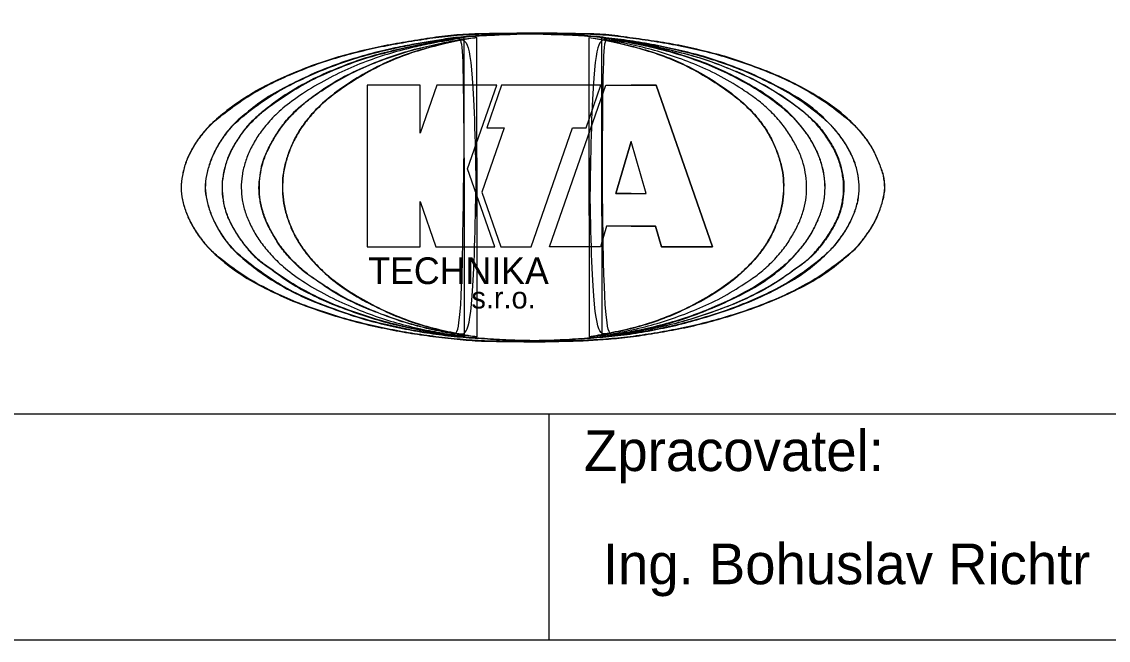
# Model space of a CAD drawing. Extents: x 25 to 46, y -50 to -20.3.
# Drawn here: x 37.705 to 42.505, y -39.8 to -37.068 of the extents above; entities that cross this region are included whole.
import ezdxf

# ---------------------------------------------------------------- set-up
doc = ezdxf.new("R2010")
doc.units = 0
doc.layers.add('_popis', color=7, linetype='Continuous')
doc.layers.add('Rozpiska_pole_6', color=7, linetype='Continuous')

msp = doc.modelspace()

# ---------------------------------------------------------------- linework, layer by layer
at = {"layer": '_popis'}
for p, q in [((39.2313, -37.3488), (39.2313, -38.0628)), ((39.465, -37.3488), (39.2313, -37.3488)), ((39.5386, -37.3488), (39.465, -37.5605)), ((39.465, -37.5605), (39.465, -37.3488)), ((39.8036, -37.3488), (39.5386, -37.3488)), ((39.675, -37.7182), (39.8036, -37.3488)), ((39.825, -37.3488), (39.7594, -37.5375)), ((40.2641, -37.3488), (39.825, -37.3488)), ((40.037, -38.0626), (40.2855, -37.3488)), ((40.1984, -37.5375), (40.2641, -37.3488)), ((40.2855, -37.3488), (40.3969, -37.3488)), ((40.3969, -37.3488), (40.5083, -37.3488)), ((40.5083, -37.3488), (40.7567, -38.0626)), ((39.8369, -37.5375), (39.7381, -37.8213)), ((39.7594, -37.5375), (39.8369, -37.5375)), ((39.9551, -38.0628), (40.1379, -37.5375)), ((40.1379, -37.5375), (40.1984, -37.5375)), ((40.3969, -37.5973), (40.3305, -37.8269)), ((40.4633, -37.8269), (40.3969, -37.5973)), ((39.795, -38.0628), (39.675, -37.7182)), ((39.7381, -37.8213), (39.8222, -38.0628)), ((39.465, -38.0628), (39.465, -37.8616)), ((39.465, -37.8616), (39.535, -38.0628)), ((40.3305, -37.8269), (40.3969, -37.8269)), ((40.3969, -37.8269), (40.4633, -37.8269)), ((40.2887, -37.9716), (40.2623, -38.0628)), ((40.3969, -37.9716), (40.2887, -37.9716)), ((40.5051, -37.9716), (40.3969, -37.9716)), ((40.5315, -38.0628), (40.5051, -37.9716)), ((39.2313, -38.0628), (39.465, -38.0628)), ((39.535, -38.0628), (39.795, -38.0628)), ((39.8222, -38.0628), (39.9551, -38.0628)), ((40.2623, -38.0628), (40.037, -38.0626)), ((40.7567, -38.0626), (40.5315, -38.0628))]:
    msp.add_line(p, q, dxfattribs=at)
for points in [[(39.2313, -37.3488), (39.2313, -38.0628), (39.465, -38.0628), (39.465, -37.8616), (39.535, -38.0628), (39.795, -38.0628), (39.675, -37.7182), (39.8036, -37.3488), (39.5386, -37.3488), (39.465, -37.5605), (39.465, -37.3488), (39.2313, -37.3488)], [(39.825, -37.3488), (39.7594, -37.5375), (39.8369, -37.5375), (39.7381, -37.8213), (39.8222, -38.0628), (39.9551, -38.0628), (40.1379, -37.5375), (40.1984, -37.5375), (40.2641, -37.3488), (39.825, -37.3488)], [(40.3969, -37.9716), (40.2887, -37.9716), (40.2623, -38.0628), (40.037, -38.0626), (40.2855, -37.3488), (40.3969, -37.3488)], [(40.3969, -37.9716), (40.5051, -37.9716), (40.5315, -38.0628), (40.7567, -38.0626), (40.5083, -37.3488), (40.3969, -37.3488)], [(40.3969, -37.8269), (40.3305, -37.8269), (40.3969, -37.5973)], [(40.3969, -37.8269), (40.4633, -37.8269), (40.3969, -37.5973)]]:
    msp.add_lwpolyline(points, dxfattribs=at)
for points, degree in [([(39.9639, -37.1182), (39.9235, -37.1188), (39.852, -37.1199), (39.7448, -37.1208), (39.642, -37.1242), (39.5347, -37.1357), (39.4277, -37.1537), (39.3201, -37.1713), (39.2128, -37.1946), (39.1051, -37.2223), (38.9975, -37.2573), (38.8906, -37.3005), (38.7817, -37.3493), (38.6736, -37.4136), (38.589, -37.4768), (38.5246, -37.5353), (38.4849, -37.5846), (38.452, -37.639), (38.4265, -37.6924), (38.4148, -37.7474), (38.4067, -37.8011), (38.4133, -37.8559), (38.4303, -37.9096), (38.4542, -37.9643), (38.4893, -38.0177), (38.5268, -38.0666), (38.5904, -38.1238), (38.6724, -38.1873), (38.7823, -38.2472), (38.8896, -38.2978), (38.9979, -38.3377), (39.1054, -38.3729), (39.2125, -38.4023), (39.3197, -38.4256), (39.427, -38.4454), (39.5348, -38.4603), (39.6419, -38.4721), (39.7493, -38.4805), (39.8565, -38.4792), (39.9639, -38.483), (40.0712, -38.4798), (40.1532, -38.4786), (40.1993, -38.4763), (40.2097, -38.4757)], 3), ([(39.9639, -37.1182), (39.8427, -37.1199), (39.7495, -37.1211), (39.6423, -37.1255), (39.5351, -37.1368), (39.4279, -37.1536), (39.3205, -37.1722), (39.2133, -37.1952), (39.1061, -37.2232), (38.9987, -37.2583), (38.8915, -37.3009), (38.7849, -37.3503), (38.6775, -37.4138), (38.5703, -37.4945), (38.5286, -37.5334), (38.4849, -37.5873), (38.4523, -37.6406), (38.4282, -37.6944), (38.4153, -37.7478), (38.4091, -37.8015), (38.4147, -37.8543), (38.431, -37.9085), (38.4551, -37.9623), (38.4888, -38.0156), (38.532, -38.0694), (38.5702, -38.1052), (38.6774, -38.1865), (38.7846, -38.2471), (38.8906, -38.2964), (38.9989, -38.3373), (39.1065, -38.3723), (39.2131, -38.4014), (39.3197, -38.425), (39.4275, -38.4446), (39.535, -38.4598), (39.6427, -38.4716), (39.7487, -38.4789), (39.8568, -38.4801), (39.9639, -38.4818), (40.0711, -38.4801), (40.1786, -38.4773), (40.2858, -38.4705), (40.3924, -38.4605), (40.4999, -38.4442), (40.6071, -38.4251), (40.7143, -38.401), (40.8218, -38.3713), (40.929, -38.336), (41.0362, -38.2945), (41.1428, -38.2446), (41.2508, -38.1813), (41.3585, -38.0978), (41.3905, -38.0692), (41.4326, -38.0159), (41.468, -37.9626), (41.4928, -37.9085), (41.5102, -37.8552), (41.5187, -37.8015), (41.5124, -37.748), (41.4939, -37.6942), (41.4698, -37.6394), (41.4378, -37.5872), (41.3924, -37.5334), (41.3593, -37.5009), (41.2509, -37.417), (41.1437, -37.3537), (41.0373, -37.3029), (40.9295, -37.2614), (40.8218, -37.2244), (40.7152, -37.1964), (40.6071, -37.1722), (40.4994, -37.1537), (40.3917, -37.1386), (40.2853, -37.125), (40.1784, -37.1211), (40.0713, -37.1192), (39.9639, -37.1182), (39.9639, -37.1182), (39.9639, -37.1182)], 3), ([(39.9639, -37.1211), (39.9997, -37.1226), (40.0713, -37.1255), (40.1787, -37.1265), (40.2858, -37.1383), (40.393, -37.1519), (40.5005, -37.1698), (40.6076, -37.1935), (40.7158, -37.2191), (40.8227, -37.2556), (40.9309, -37.2969), (41.0378, -37.3497), (41.1493, -37.4096), (41.2316, -37.4752), (41.2925, -37.5363), (41.331, -37.5848), (41.364, -37.639), (41.3885, -37.6928), (41.4013, -37.7476), (41.406, -37.8017), (41.4019, -37.8563), (41.3856, -37.9101), (41.3615, -37.9642), (41.3273, -38.0178), (41.2909, -38.0655), (41.2291, -38.1234), (41.1493, -38.1893), (41.0386, -38.2517), (40.9304, -38.3018), (40.8228, -38.3436), (40.715, -38.3773), (40.6078, -38.4072), (40.5001, -38.4295), (40.393, -38.4491), (40.2855, -38.4596), (40.1784, -38.4688), (40.0713, -38.4757), (39.9639, -38.4792), (39.8566, -38.4751), (39.7494, -38.4675), (39.6419, -38.4616), (39.5346, -38.4489), (39.4272, -38.4315), (39.3199, -38.4087), (39.2119, -38.3821), (39.1053, -38.3453), (38.9969, -38.3064), (38.8884, -38.2571), (38.7805, -38.1918), (38.696, -38.1276), (38.6313, -38.0686), (38.5928, -38.0182), (38.5608, -37.9637), (38.5367, -37.9099), (38.5218, -37.8558), (38.5123, -37.8015), (38.5206, -37.7471), (38.5345, -37.693), (38.5572, -37.6389), (38.589, -37.5849), (38.6276, -37.5322), (38.6946, -37.4726), (38.7792, -37.4054), (38.8901, -37.3461), (38.997, -37.2943), (39.1048, -37.2523), (39.2124, -37.218), (39.32, -37.1904), (39.4116, -37.1723), (39.4832, -37.1591), (39.5546, -37.1477), (39.6419, -37.1348), (39.7494, -37.1281), (39.8567, -37.1236), (39.9282, -37.122), (39.9639, -37.1211)], 3), ([(39.9639, -37.1211), (39.8567, -37.124), (39.7495, -37.1284), (39.6423, -37.1363), (39.5351, -37.1509), (39.4869, -37.1587), (39.428, -37.1694), (39.3205, -37.1913), (39.2133, -37.2188), (39.1059, -37.2532), (38.9988, -37.2952), (38.8914, -37.3463), (38.7848, -37.4063), (38.6775, -37.4883), (38.6298, -37.5333), (38.5888, -37.5872), (38.558, -37.6404), (38.5355, -37.6944), (38.5215, -37.7477), (38.5153, -37.8015), (38.5226, -37.8551), (38.5377, -37.9083), (38.5613, -37.9622), (38.5928, -38.0158), (38.6349, -38.0696), (38.6775, -38.11), (38.7847, -38.1919), (38.8914, -38.256), (38.9986, -38.3054), (39.1058, -38.3452), (39.2132, -38.3807), (39.3204, -38.4082), (39.4276, -38.4306), (39.535, -38.4482), (39.6422, -38.4605), (39.7494, -38.4678), (39.8567, -38.4745), (39.9639, -38.4779), (40.0711, -38.4751), (40.1786, -38.4684), (40.2852, -38.4594), (40.3924, -38.4476), (40.4999, -38.4291), (40.607, -38.4061), (40.7142, -38.3769), (40.8217, -38.3426), (40.9289, -38.3011), (41.0361, -38.2512), (41.1435, -38.1886), (41.2507, -38.1028), (41.285, -38.0695), (41.3277, -38.0156), (41.3608, -37.9624), (41.3849, -37.9085), (41.4, -37.8553), (41.4045, -37.802), (41.4, -37.7479), (41.3871, -37.6947), (41.3636, -37.6408), (41.331, -37.5872), (41.2883, -37.5333), (41.2507, -37.4952), (41.1436, -37.4105), (41.0362, -37.3496), (40.929, -37.298), (40.8218, -37.256), (40.7144, -37.2206), (40.6073, -37.1937), (40.5001, -37.1707), (40.3926, -37.1526), (40.2855, -37.1385), (40.1786, -37.1283), (40.0714, -37.1249), (39.9639, -37.1211), (39.9639, -37.1211), (39.9639, -37.1211)], 3), ([(39.6598, -37.1392), (39.6542, -37.1395), (39.6124, -37.142), (39.5349, -37.1558), (39.4279, -37.1771), (39.3197, -37.2014), (39.2116, -37.2305), (39.1047, -37.2712), (38.9961, -37.3167), (38.8874, -37.3779), (38.8068, -37.4345), (38.7427, -37.4867), (38.6988, -37.5289), (38.6605, -37.5856), (38.6272, -37.6379), (38.6063, -37.6931), (38.5939, -37.7473), (38.5881, -37.8016), (38.5941, -37.8555), (38.605, -37.9105), (38.6297, -37.9637), (38.6615, -38.0175), (38.7024, -38.072), (38.7425, -38.1172), (38.8103, -38.1619), (38.8864, -38.2219), (38.9959, -38.2806), (39.1038, -38.3273), (39.2116, -38.3644), (39.3184, -38.3987), (39.4269, -38.4217), (39.5198, -38.4409), (39.5976, -38.4528), (39.6396, -38.4563), (39.6602, -38.458)], 3), ([(39.6602, -38.458), (39.5987, -38.4522), (39.5345, -38.4427), (39.4273, -38.4217), (39.3195, -38.397), (39.212, -38.3641), (39.1053, -38.3263), (38.9986, -38.2801), (38.891, -38.2205), (38.7832, -38.1443), (38.7543, -38.1238), (38.7017, -38.0697), (38.6611, -38.0148), (38.6301, -37.9622), (38.6069, -37.9092), (38.5948, -37.8548), (38.59, -37.8012), (38.5948, -37.7486), (38.6074, -37.694), (38.6284, -37.64), (38.66, -37.587), (38.6984, -37.5334), (38.753, -37.4787), (38.7825, -37.4546), (38.891, -37.3782), (38.9993, -37.3178), (39.1062, -37.2713), (39.2118, -37.2324), (39.3215, -37.2018), (39.4277, -37.1776), (39.5355, -37.1561), (39.643, -37.1403), (39.6598, -37.1392), (39.6602, -38.458), (39.6598, -37.1392)], 3), ([(39.6598, -37.1392), (39.5441, -37.1576), (39.4279, -37.1817), (39.3201, -37.2112), (39.2125, -37.2476), (39.1063, -37.2938), (38.9991, -37.3506), (38.8916, -37.4218), (38.8243, -37.4796), (38.7764, -37.5337), (38.7386, -37.5868), (38.7102, -37.6399), (38.6896, -37.6943), (38.6775, -37.7484), (38.6738, -37.8014), (38.678, -37.8554), (38.6912, -37.9085), (38.7133, -37.9621), (38.7422, -38.0162), (38.7811, -38.0693), (38.829, -38.1228), (38.8926, -38.1785), (38.9988, -38.2489), (39.1066, -38.3041), (39.2136, -38.3496), (39.3208, -38.3874), (39.4276, -38.4163), (39.5351, -38.4385), (39.6113, -38.4511), (39.6602, -38.458), (39.6598, -37.1392), (39.6602, -38.458)], 3), ([(39.7161, -38.4596), (39.6914, -38.4575), (39.6304, -38.4523), (39.5347, -38.4318), (39.4265, -38.4074), (39.3198, -38.3704), (39.2116, -38.3288), (39.1018, -38.2769), (39.021, -38.2196), (38.9493, -38.1723), (38.9019, -38.1253), (38.8532, -38.0728), (38.8201, -38.0165), (38.7893, -37.964), (38.7686, -37.9101), (38.7572, -37.8559), (38.7513, -37.8017), (38.7578, -37.7476), (38.7662, -37.6929), (38.7884, -37.6393), (38.817, -37.5858), (38.8518, -37.5308), (38.8972, -37.476), (38.9485, -37.4304), (39.0183, -37.3777), (39.1027, -37.3224), (39.2113, -37.2692), (39.3191, -37.2272), (39.4263, -37.1919), (39.5343, -37.1674), (39.6305, -37.1475), (39.6915, -37.1406), (39.7161, -37.1377)], 3), ([(39.7161, -38.4596), (39.6424, -38.452), (39.5346, -38.4316), (39.4284, -38.4058), (39.3206, -38.3701), (39.2131, -38.3279), (39.1064, -38.2754), (38.9989, -38.2052), (38.9585, -38.1768), (38.9001, -38.1227), (38.8538, -38.0696), (38.8196, -38.0157), (38.7902, -37.9621), (38.7697, -37.9085), (38.7581, -37.856), (38.7533, -37.8017), (38.7581, -37.7475), (38.7681, -37.6945), (38.7886, -37.6412), (38.8175, -37.5866), (38.8517, -37.5335), (38.8964, -37.4796), (38.9552, -37.426), (38.9994, -37.3924), (39.1063, -37.3233), (39.213, -37.2702), (39.3208, -37.2277), (39.4272, -37.1935), (39.5345, -37.1677), (39.6424, -37.1471), (39.7161, -37.1377), (39.7161, -38.4596), (39.7161, -37.1377)], 3), ([(39.7161, -37.1377), (39.6915, -37.1413), (39.6306, -37.1502), (39.5345, -37.1738), (39.426, -37.2027), (39.3179, -37.2449), (39.2101, -37.3004), (39.1156, -37.3622), (39.0382, -37.4217), (38.9841, -37.4775), (38.9415, -37.531), (38.9092, -37.5853), (38.8859, -37.6396), (38.8686, -37.6935), (38.8574, -37.7474), (38.8558, -37.8015), (38.8589, -37.8555), (38.8693, -37.9097), (38.8885, -37.9631), (38.9121, -38.0178), (38.946, -38.0711), (38.9886, -38.1254), (39.0426, -38.1786), (39.1162, -38.2399), (39.21, -38.2985), (39.3183, -38.352), (39.4258, -38.3958), (39.5342, -38.4259), (39.631, -38.446), (39.6914, -38.4557), (39.7161, -38.4596)], 3), ([(39.7161, -37.1377), (39.6424, -37.1494), (39.5353, -37.174), (39.4276, -37.2044), (39.3205, -37.2459), (39.2132, -37.3011), (39.1061, -37.3706), (39.0357, -37.4266), (38.9836, -37.4798), (38.9415, -37.5336), (38.9099, -37.5869), (38.8865, -37.6407), (38.8694, -37.6943), (38.8589, -37.7481), (38.8565, -37.8013), (38.86, -37.8551), (38.8706, -37.9089), (38.8887, -37.9621), (38.9128, -38.0157), (38.9461, -38.0695), (38.9877, -38.1221), (39.0416, -38.1762), (39.106, -38.2294), (39.213, -38.2978), (39.3203, -38.3513), (39.4274, -38.394), (39.5356, -38.425), (39.6423, -38.4473), (39.7161, -38.4596), (39.7161, -37.1377), (39.7161, -38.4596)], 3), ([(40.2097, -38.4757), (40.235, -38.4743), (40.296, -38.4699), (40.3931, -38.4618), (40.5, -38.4443), (40.6076, -38.426), (40.715, -38.4017), (40.8225, -38.3721), (40.93, -38.3366), (41.0376, -38.2954), (41.1457, -38.2449), (41.256, -38.1823), (41.3346, -38.1179), (41.398, -38.0648), (41.4318, -38.0169), (41.4691, -37.965), (41.4932, -37.9098), (41.5113, -37.8562), (41.5216, -37.8018), (41.5143, -37.7463), (41.4938, -37.6932), (41.471, -37.6383), (41.4374, -37.5837), (41.3984, -37.5387), (41.3381, -37.4793), (41.2557, -37.4172), (41.1464, -37.3533), (41.0387, -37.3015), (40.9301, -37.2615), (40.8235, -37.2229), (40.7151, -37.1961), (40.6078, -37.1712), (40.4996, -37.1531), (40.3922, -37.1391), (40.2856, -37.1225), (40.1783, -37.1213), (40.0712, -37.119), (39.9997, -37.1184), (39.9639, -37.1182)], 3), ([(40.2117, -37.1377), (40.2364, -37.1413), (40.2973, -37.1502), (40.3933, -37.1738), (40.5018, -37.2027), (40.6099, -37.2449), (40.7178, -37.3004), (40.8123, -37.3622), (40.8896, -37.4217), (40.9437, -37.4775), (40.9863, -37.531), (41.0186, -37.5853), (41.0419, -37.6396), (41.0592, -37.6935), (41.0705, -37.7474), (41.0721, -37.8015), (41.069, -37.8555), (41.0585, -37.9097), (41.0394, -37.9631), (41.0158, -38.0178), (40.9819, -38.0711), (40.9392, -38.1254), (40.8852, -38.1786), (40.8116, -38.2399), (40.7178, -38.2985), (40.6095, -38.352), (40.502, -38.3958), (40.3936, -38.4259), (40.2969, -38.446), (40.2364, -38.4557), (40.2118, -38.4596)], 3), ([(40.2117, -37.1377), (40.2855, -37.1494), (40.3926, -37.174), (40.5002, -37.2044), (40.6073, -37.2459), (40.7146, -37.3011), (40.8217, -37.3706), (40.8921, -37.4266), (40.9442, -37.4798), (40.9863, -37.5336), (41.0179, -37.5869), (41.0413, -37.6407), (41.0584, -37.6943), (41.069, -37.7481), (41.0713, -37.8013), (41.0678, -37.8551), (41.0573, -37.9089), (41.0391, -37.9621), (41.0151, -38.0157), (40.9817, -38.0695), (40.9402, -38.1221), (40.8863, -38.1762), (40.8219, -38.2294), (40.7148, -38.2978), (40.6075, -38.3513), (40.5005, -38.394), (40.3922, -38.425), (40.2855, -38.4473), (40.2118, -38.4596), (40.2117, -37.1377), (40.2118, -38.4596)], 3), ([(40.2118, -38.4596), (40.2855, -38.452), (40.3932, -38.4316), (40.4994, -38.4058), (40.6072, -38.3701), (40.7147, -38.3279), (40.8214, -38.2754), (40.9289, -38.2052), (40.9694, -38.1768), (41.0277, -38.1227), (41.074, -38.0696), (41.1082, -38.0157), (41.1376, -37.9621), (41.1581, -37.9085), (41.1697, -37.856), (41.1745, -37.8017), (41.1698, -37.7475), (41.1598, -37.6945), (41.1393, -37.6412), (41.1104, -37.5866), (41.0762, -37.5335), (41.0315, -37.4796), (40.9726, -37.426), (40.9284, -37.3924), (40.8216, -37.3233), (40.7149, -37.2702), (40.6071, -37.2277), (40.5006, -37.1935), (40.3934, -37.1677), (40.2854, -37.1471), (40.2117, -37.1377), (40.2118, -38.4596), (40.2117, -37.1377)], 3), ([(40.2677, -38.458), (40.284, -38.4558), (40.3258, -38.4501), (40.4035, -38.4371), (40.5008, -38.4174), (40.6085, -38.3886), (40.7155, -38.3503), (40.8232, -38.3045), (40.932, -38.2499), (41.0253, -38.1891), (41.0971, -38.127), (41.1461, -38.0714), (41.1865, -38.0185), (41.2147, -37.9634), (41.2378, -37.9101), (41.2513, -37.8558), (41.2553, -37.8018), (41.2516, -37.7474), (41.2393, -37.693), (41.2185, -37.6388), (41.1896, -37.5846), (41.1507, -37.5313), (41.1012, -37.4743), (41.0268, -37.412), (40.932, -37.3501), (40.8238, -37.2935), (40.7167, -37.2461), (40.6086, -37.2104), (40.498, -37.18), (40.3844, -37.1566), (40.3067, -37.145), (40.2681, -37.1392)], 3), ([(40.2681, -37.1392), (40.2737, -37.1395), (40.3154, -37.142), (40.3929, -37.1558), (40.4999, -37.1771), (40.6081, -37.2014), (40.7162, -37.2305), (40.8231, -37.2712), (40.9318, -37.3167), (41.0404, -37.3779), (41.1211, -37.4345), (41.1851, -37.4867), (41.229, -37.5289), (41.2673, -37.5856), (41.3007, -37.6379), (41.3216, -37.6931), (41.334, -37.7473), (41.3397, -37.8016), (41.3338, -37.8555), (41.3228, -37.9105), (41.2981, -37.9637), (41.2664, -38.0175), (41.2255, -38.072), (41.1853, -38.1172), (41.1176, -38.1619), (41.0414, -38.2219), (40.9319, -38.2806), (40.824, -38.3273), (40.7162, -38.3644), (40.6094, -38.3987), (40.501, -38.4217), (40.408, -38.4409), (40.3303, -38.4528), (40.2882, -38.4563), (40.2677, -38.458)], 3), ([(40.2677, -38.458), (40.3292, -38.4522), (40.3933, -38.4427), (40.5006, -38.4217), (40.6083, -38.397), (40.7158, -38.3641), (40.8225, -38.3263), (40.9293, -38.2801), (41.0368, -38.2205), (41.1446, -38.1443), (41.1735, -38.1238), (41.2261, -38.0697), (41.2667, -38.0148), (41.2978, -37.9622), (41.3209, -37.9092), (41.3331, -37.8548), (41.3378, -37.8012), (41.3331, -37.7486), (41.3205, -37.694), (41.2994, -37.64), (41.2679, -37.587), (41.2295, -37.5334), (41.1748, -37.4787), (41.1454, -37.4546), (41.0368, -37.3782), (40.9285, -37.3178), (40.8217, -37.2713), (40.716, -37.2324), (40.6063, -37.2018), (40.5001, -37.1776), (40.3924, -37.1561), (40.2849, -37.1403), (40.2681, -37.1392), (40.2677, -38.458), (40.2681, -37.1392)], 3), ([(40.2681, -37.1392), (40.3837, -37.1576), (40.4999, -37.1817), (40.6077, -37.2112), (40.7153, -37.2476), (40.8215, -37.2938), (40.9288, -37.3506), (41.0363, -37.4218), (41.1036, -37.4796), (41.1514, -37.5337), (41.1893, -37.5868), (41.2177, -37.6399), (41.2382, -37.6943), (41.2503, -37.7484), (41.254, -37.8014), (41.2498, -37.8554), (41.2367, -37.9085), (41.2146, -37.9621), (41.1857, -38.0162), (41.1468, -38.0693), (41.0988, -38.1228), (41.0352, -38.1785), (40.929, -38.2489), (40.8213, -38.3041), (40.7142, -38.3496), (40.607, -38.3874), (40.5003, -38.4163), (40.3928, -38.4385), (40.3165, -38.4511), (40.2677, -38.458), (40.2681, -37.1392), (40.2677, -38.458)], 3), ([(39.6602, -38.458), (39.6602, -38.458), (39.6602, -38.458), (39.6602, -38.458)], 2), ([(40.2118, -38.4596), (40.2118, -38.4596), (40.2118, -38.4596), (40.2118, -38.4596)], 2)]:
    msp.add_open_spline(points, degree=degree, dxfattribs=at)
at = {"layer": 'Rozpiska_pole_6'}
for p, q in [((27, -38.8), (44, -38.8)), ((40.035, -39.8), (40.035, -38.8))]:
    msp.add_line(p, q, dxfattribs=at)
msp.add_lwpolyline([(27, -34.8), (44, -34.8), (44, -39.8), (27, -39.8)], close=True, dxfattribs=at)

# ---------------------------------------------------------------- texts
at = {"layer": '_popis'}
for s, height, p in [('TECHNIKA', 0.11795, (39.2362, -38.2268)), ('s.r.o.', 0.09543, (39.6919, -38.3347))]:
    msp.add_text(s, height=height, dxfattribs=at).set_placement(p)
at = {"layer": 'Rozpiska_pole_6'}
for s, p in [('Zpracovatel:', (40.1896, -39.0527)), ('Ing. Bohuslav Richtr', (40.2725, -39.5527))]:
    msp.add_text(s, height=0.18, dxfattribs=at).set_placement(p)

doc.saveas('drawing.dxf')
